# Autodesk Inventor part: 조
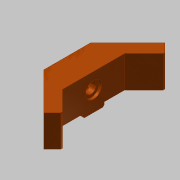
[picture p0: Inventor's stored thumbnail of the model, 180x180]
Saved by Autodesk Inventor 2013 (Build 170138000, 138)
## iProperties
Created: 2019-04
Part Number: 조
Material: 알루미늄 6061
Document SubType Name: Modeling
Designer: mduedu
Density: 1 g/cm^3
Author: mduedu
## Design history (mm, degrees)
sketch "스케치1"
  geometry: L1 (45.962, 0)-(0, -45.962); L2 (0, -45.962)-(-45.962, 0); L3 (-45.962, 0)-(0, 45.962); L4 (0, 45.962)-(45.962, 0); L5 (45.962, 0)-(-45.962, 0); L6 (0, -45.962)-(0, 45.962); 1 further point
  constraints: 12 end point, 2 midpoint, 2 parallel, 2 perpendicular, 1 horizontal
  dimensions: "d0" = 65 distance of L1.end L2.end
extrude "돌출1" new body sketch "스케치1" distance "d2" = 27; taper "d3" = 0 deg
chamfer "모따기1" distance "d4" = 25; stored, may be unused: second distance "d5" = 2, angle "d6" = 45 deg
sketch "스케치2"
  geometry: L1 (-17.678, 28.284)-(-45.962, 0) reference; L2 (-17.678, 28.284)-(17.678, 28.284) reference; L3 (45.962, 0)-(17.678, 28.284) reference; L4 (-45.962, 0)-(0, -45.962) reference; L5 (0, -45.962)-(45.962, 0) reference; L6 (-23.536, 8.284)-(23.536, 8.284); L7 (-23.536, 8.284)-(-38.891, -7.071); L8 (38.891, -7.071)-(23.536, 8.284); 1 further point
  constraints: 6 end point, 3 parallel, 2 point on line
  dimensions: "d7" = 20 distance between parallel lines of L6 L2; "d8" = 10 distance between parallel lines of L1 L7; "d9" = 10 distance between parallel lines of L3 L8
extrude "돌출2" cut sketch "스케치2" stored distance "d10" = 27; taper "d11" = 0 deg
sketch "스케치3"
  geometry: L1 (63.64, -27)-(63.64, 0) reference; L2 (56.569, -27)-(63.64, -27) reference; L3 (-28.284, -27)-(-28.284, 0) reference; L4 (-28.284, -27)-(-21.213, -27) reference; L5 (63.64, -27)-(25.678, -27); L6 (25.678, -27)-(25.678, -24); L7 (25.678, -24)-(63.64, -24); L8 (63.64, -24)-(63.64, -27); L9 (-28.284, -27)-(9.678, -27); L10 (9.678, -27)-(9.678, -24); L11 (9.678, -24)-(-28.284, -24); L12 (-28.284, -24)-(-28.284, -27); L13 (41.213, 0)-(-5.858, 0) reference; L14 (17.678, -27)-(17.678, 0)
  constraints: 18 end point, 4 parallel, 2 horizontal, 2 perpendicular, 1 midpoint, 1 symmetric about line
  dimensions: "d12" = 3 distance between parallel lines of L5 L7; "d14" = 16 distance between parallel lines of L10 L6
extrude "돌출3" cut sketch "스케치3" stored distance "d15" = 27; taper "d16" = 0 deg
sketch "스케치4"
  geometry: L1 (31.536, -27)-(15.536, -27) reference; L2 (31.536, -24)-(47.071, -24) reference; 3 further points
  constraints: 1 midpoint, 1 vertical alignment
  dimensions: "d17" = 12 distance from line of L2 point (23.536, -12)
hole "구멍1" sketch "스케치4" at (23.536, -12) diameter "d18" = 8; stored, may be unused: countersink angle "d22" = 90 deg, drill point angle "d24" = 118 deg; dims "d19" = 6, "d20" = 12.5, "d21" = 2, "d23" = 14
node "작업 평면1"
sketch "스케치5"
  geometry: L1 (0, -15)-(0, 0); L2 (-50, -4)-(50, -4); L3 (50, -4)-(50, -1.75); L4 (-50, -1.75)-(-50, -4); L5 (12, -1.75)-(12, -2.75); L6 (12, -2.75)-(-12, -2.75); L7 (-12, -2.75)-(-12, -1.75); L8 (50, -1.75)-(12, -1.75); L9 (-12, -1.75)-(-50, -1.75); C1 r 4 at (0, 0) reference; 2 further points
  constraints: 18 end point, 4 parallel, 2 midpoint, 2 vertical, 2 vertical alignment, 1 collinear, 1 horizontal, 1 perpendicular, 1 tangent
  dimensions: "d26" = 2.5 diameter of L6 L2; "d28" = 4.5 diameter of L8 L2; "d29" = 24 distance of L5.end L6.end; "d30" = 100 distance between parallel lines of L3 L4
revolve "회전1" sketch "스케치5" stored, may be unused: angle "d31" = 90 deg
chamfer "모따기2" distance "d32" = 1; stored, may be unused: second distance "d33" = 2, angle "d34" = 45 deg
chamfer "모따기3" distance "d35" = 1; stored, may be unused: second distance "d36" = 2, angle "d37" = 45 deg
node "솔리드1"
other parameters: "d25" = -5
